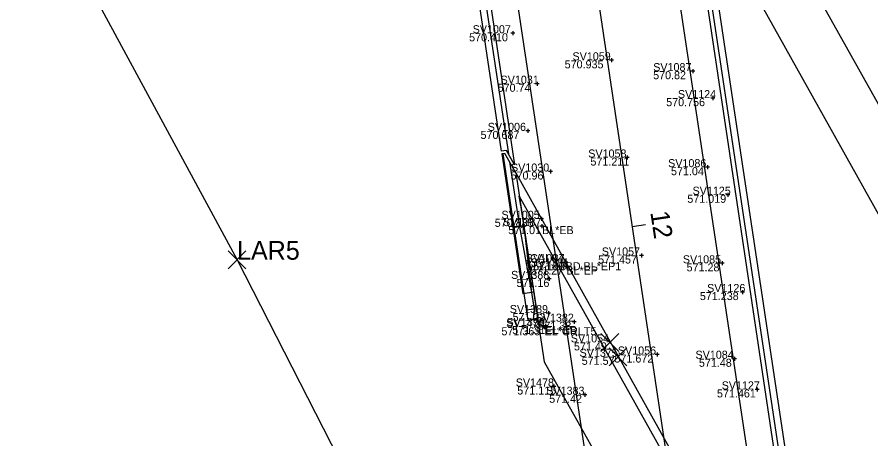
# Model space of a CAD drawing. Extents: x 6334 to 41599, y 9030 to 59113.
# Drawn here: x 21051.8 to 21179.4, y 34183.1 to 34246.1 of the extents above; entities that cross this region are included whole.
import ezdxf

# ---------------------------------------------------------------- set-up
doc = ezdxf.new("R2010")
doc.units = 0
for name, color, linetype in [('BR_P_Sub_Hidden', 7, 'Continuous'), ('BR_X_Gen_Approach_Slab', 7, 'Continuous'), ('BR_X_Slab_Centerline', 7, 'Continuous'), ('BR_X_SV_Deck_Top', 7, 'Continuous'), ('BR_X_SV_Deck_Top_Text', 7, 'Continuous'), ('GE_P_CL_20', 7, 'Continuous'), ('GK_Visualization', 7, 'Continuous'), ('PM_X_CL_Double_Solid', 7, 'Continuous'), ('PV_X_EOP', 7, 'Continuous'), ('PV_X_Shoulder', 7, 'Continuous'), ('RW_X_Esmt_LA', 7, 'Continuous'), ('SV_X_Random_Point', 7, 'Continuous'), ('SV_X_Shot_Marker', 7, 'Continuous'), ('SV_X_Text_Comment', 7, 'Continuous'), ('SV_X_Text_Elevation', 7, 'Continuous'), ('SV_X_Text_Name', 7, 'Continuous')]:
    doc.layers.add(name, color=color, linetype=linetype)

msp = doc.modelspace()

# ---------------------------------------------------------------- linework, layer by layer
at = {"layer": 'BR_P_Sub_Hidden'}
msp.add_line((21127.04, 34217.96), (21126.83, 34219.36), dxfattribs=at)
at = {"layer": 'BR_X_Gen_Approach_Slab'}
for p, q in [((21126.83, 34219.36), (21130.54, 34194.64)), ((21126.83, 34219.36), (21171.07, 34140.25)), ((21130.54, 34194.64), (21174.78, 34115.53))]:
    msp.add_line(p, q, dxfattribs=at)
at = {"layer": 'BR_X_Slab_Centerline'}
msp.add_line((21088.12, 34584.84), (21156.74, 34127.95), dxfattribs=at)
at = {"layer": 'BR_X_SV_Deck_Top'}
for p, q in [((21072.33, 34570.99), (21124.14, 34226.08)), ((21073.52, 34569.83), (21125.21, 34225.67)), ((21074.44, 34568.18), (21126.13, 34224.03)), ((21118.68, 34489.07), (21170.37, 34144.92)), ((21119.6, 34487.43), (21171.29, 34143.27)), ((21120.67, 34487.02), (21172.48, 34142.11)), ((21124.92, 34226.2), (21124.14, 34226.08)), ((21124.69, 34225.74), (21124.2, 34225.67)), ((21124.2, 34225.67), (21127.34, 34204.76)), ((21124.36, 34225.69), (21128.1, 34200.83)), ((21126.31, 34222.86), (21124.69, 34225.74)), ((21126.13, 34224.03), (21124.92, 34226.2)), ((21125.38, 34224.51), (21126.84, 34214.8)), ((21126.07, 34223.28), (21171.76, 34141.58)), ((21126.31, 34222.86), (21129.58, 34201.05)), ((21127.5, 34214.9), (21125.85, 34214.65)), ((21126.84, 34214.8), (21128.66, 34204.96)), ((21127.5, 34214.9), (21128.66, 34204.96)), ((21128.99, 34205.01), (21127.34, 34204.76)), ((21128.66, 34204.96), (21129.03, 34202.49)), ((21129.36, 34202.54), (21127.87, 34202.31)), ((21129.03, 34202.49), (21128.92, 34200.96)), ((21129.58, 34201.05), (21128.1, 34200.83)), ((21129.58, 34201.05), (21128.1, 34200.83))]:
    msp.add_line(p, q, dxfattribs=at)
at = {"layer": 'BR_X_SV_Deck_Top_Text'}
for p, q in [((21126.18, 34243.69), (21125.58, 34243.69)), ((21125.88, 34243.99), (21125.88, 34243.39)), ((21156.06, 34234), (21155.46, 34234)), ((21155.76, 34234.3), (21155.76, 34233.7)), ((21128.1, 34229.41), (21128.1, 34228.81)), ((21128.4, 34229.11), (21127.8, 34229.11)), ((21158.27, 34219.57), (21157.67, 34219.57)), ((21157.97, 34219.87), (21157.97, 34219.27)), ((21130.44, 34215.98), (21129.84, 34215.98)), ((21130.14, 34216.28), (21130.14, 34215.68)), ((21134.06, 34209.5), (21133.46, 34209.5)), ((21133.76, 34209.8), (21133.76, 34209.2)), ((21160.16, 34205.34), (21160.16, 34204.74)), ((21160.46, 34205.04), (21159.86, 34205.04)), ((21162.68, 34190.5), (21162.08, 34190.5)), ((21162.38, 34190.8), (21162.38, 34190.2))]:
    msp.add_line(p, q, dxfattribs=at)
at = {"layer": 'GE_P_CL_20'}
msp.add_line((21143.69, 34214.83), (21145.67, 34215.12), dxfattribs=at)
at = {"layer": 'GK_Visualization'}
for p, q in [((21084.27, 34610.45), (21262.51, 33423.7)), ((21084.27, 34610.45), (21262.51, 33423.7)), ((21083.32, 34208.53), (21085.99, 34211.2)), ((21083.32, 34211.2), (21085.99, 34208.53))]:
    msp.add_line(p, q, dxfattribs=at)
at = {"layer": 'PM_X_CL_Double_Solid'}
msp.add_line((21084.27, 34610.45), (21262.51, 33423.7), dxfattribs=at)
at = {"layer": 'PV_X_EOP'}
for p, q in [((21096.14, 34612.23), (21274.38, 33425.48)), ((21072.4, 34608.67), (21250.65, 33421.92)), ((21109.92, 34359.21), (21575.4, 33526.9))]:
    msp.add_line(p, q, dxfattribs=at)
at = {"layer": 'PV_X_Shoulder'}
msp.add_line((21102.94, 34355.3), (21568.42, 33523), dxfattribs=at)
at = {"layer": 'RW_X_Esmt_LA'}
for p, q in [((21020.77, 34328.02), (21084.66, 34209.87)), ((21084.66, 34209.87), (21370.15, 33651.46))]:
    msp.add_line(p, q, dxfattribs=at)
at = {"layer": 'SV_X_Random_Point'}
for p, q in [((21139.03, 34196.18), (21141.69, 34198.85)), ((21139.03, 34198.85), (21141.69, 34196.18)), ((21140.24, 34194.04), (21142.9, 34196.71)), ((21140.24, 34196.71), (21142.9, 34194.04))]:
    msp.add_line(p, q, dxfattribs=at)
at = {"layer": 'SV_X_Shot_Marker'}
for p, q in [((21140.93, 34239.65), (21140.33, 34239.65)), ((21140.63, 34239.95), (21140.63, 34239.35)), ((21152.75, 34238.33), (21152.75, 34237.73)), ((21153.05, 34238.03), (21152.45, 34238.03)), ((21129.79, 34236.15), (21129.19, 34236.15)), ((21129.49, 34236.45), (21129.49, 34235.85)), ((21143.24, 34225.13), (21142.64, 34225.13)), ((21142.94, 34225.43), (21142.94, 34224.83)), ((21131.8, 34223.04), (21131.2, 34223.04)), ((21131.5, 34223.34), (21131.5, 34222.74)), ((21155.24, 34223.69), (21154.64, 34223.69)), ((21154.94, 34223.99), (21154.94, 34223.39)), ((21130.52, 34214.89), (21129.92, 34214.89)), ((21130.22, 34215.19), (21130.22, 34214.59)), ((21145.37, 34210.5), (21144.77, 34210.5)), ((21145.07, 34210.8), (21145.07, 34210.2)), ((21134.06, 34209.5), (21133.46, 34209.5)), ((21133.76, 34209.8), (21133.76, 34209.2)), ((21133.87, 34209.16), (21133.87, 34208.56)), ((21157.42, 34209.33), (21156.82, 34209.33)), ((21157.12, 34209.63), (21157.12, 34209.03)), ((21134.17, 34208.86), (21133.57, 34208.86)), ((21131.61, 34207), (21131.01, 34207)), ((21131.31, 34207.3), (21131.31, 34206.7)), ((21131.47, 34201.9), (21130.87, 34201.9)), ((21131.17, 34202.2), (21131.17, 34201.6)), ((21130.6, 34200.08), (21130.6, 34199.48)), ((21130.74, 34200.27), (21130.74, 34199.67)), ((21135.32, 34200.61), (21134.72, 34200.61)), ((21135.02, 34200.91), (21135.02, 34200.31)), ((21130.9, 34199.78), (21130.3, 34199.78)), ((21131.04, 34199.97), (21130.44, 34199.97)), ((21147.73, 34195.71), (21147.13, 34195.71)), ((21147.43, 34196.01), (21147.43, 34195.41)), ((21159.29, 34195.08), (21158.69, 34195.08)), ((21158.99, 34195.38), (21158.99, 34194.78)), ((21131.98, 34191.23), (21131.98, 34190.63)), ((21132.28, 34190.93), (21131.68, 34190.93)), ((21136.63, 34190), (21136.63, 34189.4)), ((21136.93, 34189.7), (21136.33, 34189.7))]:
    msp.add_line(p, q, dxfattribs=at)

# ---------------------------------------------------------------- texts
at = {"layer": 'BR_X_SV_Deck_Top_Text'}
for s, p in [('SV1007', (21119.86, 34243.69)), ('570.410', (21119.33, 34242.49)), ('SV1124', (21150.53, 34234)), ('570.756', (21148.78, 34232.8)), ('SV1006', (21122.12, 34229.11)), ('570.687', (21121.04, 34227.91)), ('SV1125', (21152.72, 34219.57)), ('571.019', (21151.94, 34218.37)), ('SV1005', (21124.17, 34215.98)), ('570.885', (21123.16, 34214.78)), ('SV1004', (21127.81, 34209.5)), ('571.180', (21127.8, 34208.3)), ('BD BL*EP1', (21133.76, 34208.3)), ('SV1126', (21154.9, 34205.04)), ('571.238', (21153.81, 34203.84)), ('SV1127', (21157.07, 34190.5)), ('571.461', (21156.37, 34189.3))]:
    msp.add_text(s, height=1.2, dxfattribs=at).set_placement(p)
at = {"layer": 'GE_P_CL_20'}
msp.add_text('12', height=2.8, rotation=278.5417, dxfattribs=at).set_placement((21146.4, 34216.96))
at = {"layer": 'GK_Visualization'}
msp.add_text('LAR5', height=2.8, dxfattribs=at).set_placement((21084.66, 34209.87))
at = {"layer": 'SV_X_Text_Comment'}
for s, p in [('BL*EB', (21130.22, 34213.69)), ('BL*EP', (21133.87, 34207.66)), ('EL*GRLT5', (21130.6, 34198.58)), ('EL*EB', (21130.74, 34198.77))]:
    msp.add_text(s, height=1.2, dxfattribs=at).set_placement(p)
at = {"layer": 'SV_X_Text_Elevation'}
for s, p in [('570.935', (21133.61, 34238.45)), ('570.82', (21146.83, 34236.83)), ('570.74', (21123.59, 34234.95)), ('571.211', (21137.46, 34223.93)), ('570.96', (21125.53, 34221.84)), ('571.04', (21149.5, 34222.49)), ('571.01', (21125.17, 34213.69)), ('571.457', (21138.61, 34209.3)), ('571.18', (21128.92, 34208.3)), ('571.28', (21151.83, 34208.13)), ('571.27', (21128.48, 34207.66)), ('571.16', (21126.42, 34205.8)), ('571.23', (21125.82, 34200.7)), ('571.38', (21129.69, 34199.41)), ('571.363', (21124.16, 34198.58)), ('571.31', (21125.78, 34198.77)), ('571.49', (21135, 34196.32)), ('571.57', (21136.16, 34194.17)), ('571.672', (21141.05, 34194.51)), ('571.48', (21153.67, 34193.88)), ('571.115', (21126.53, 34189.73)), ('571.42', (21131.29, 34188.5))]:
    msp.add_text(s, height=1.2, dxfattribs=at).set_placement(p)
at = {"layer": 'SV_X_Text_Name'}
for s, p in [('SV1059', (21134.78, 34239.65)), ('SV1087', (21146.84, 34238.03)), ('SV1031', (21124.03, 34236.15)), ('SV1058', (21137.13, 34225.13)), ('SV1030', (21125.59, 34223.04)), ('SV1086', (21149.07, 34223.69)), ('SV1387', (21124.4, 34214.89)), ('SV1057', (21139.16, 34210.5)), ('CALC7', (21128.44, 34209.5)), ('SV1085', (21151.27, 34209.33)), ('SV1381', (21128.53, 34208.86)), ('SV1388', (21125.6, 34207)), ('SV1389', (21125.41, 34201.9)), ('SV1382', (21129.27, 34200.61)), ('SV1479', (21124.87, 34199.78)), ('SV1390', (21124.92, 34199.97)), ('SV1054', (21134.53, 34197.52)), ('SV1375', (21135.83, 34195.37)), ('SV1056', (21141.56, 34195.71)), ('SV1084', (21153.16, 34195.08)), ('SV1478', (21126.3, 34190.93)), ('SV1383', (21130.86, 34189.7))]:
    msp.add_text(s, height=1.2, dxfattribs=at).set_placement(p)

doc.saveas('drawing.dxf')
